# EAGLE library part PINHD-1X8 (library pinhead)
PIN HEADER
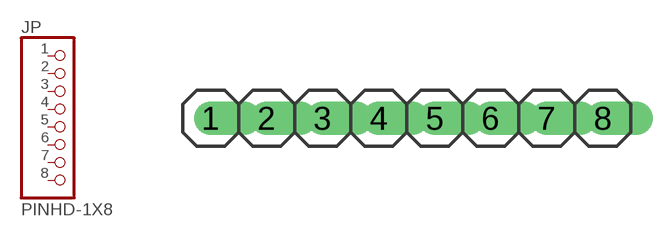
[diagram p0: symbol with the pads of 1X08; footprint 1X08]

Designator prefix JP

## PINHD-1X8  [1X08]
1  1  pas
2  2  pas
3  3  pas
4  4  pas
5  5  pas
6  6  pas
7  7  pas
8  8  pas

## Footprint 1X08 (pad centres in mm)
PIN HEADER
drill 1.016 offset: 1 -8.89,0; 2 -6.35,0; 3 -3.81,0; 4 -1.27,0; 5 1.27,0; 6 3.81,0; 7 6.35,0; 8 8.89,0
